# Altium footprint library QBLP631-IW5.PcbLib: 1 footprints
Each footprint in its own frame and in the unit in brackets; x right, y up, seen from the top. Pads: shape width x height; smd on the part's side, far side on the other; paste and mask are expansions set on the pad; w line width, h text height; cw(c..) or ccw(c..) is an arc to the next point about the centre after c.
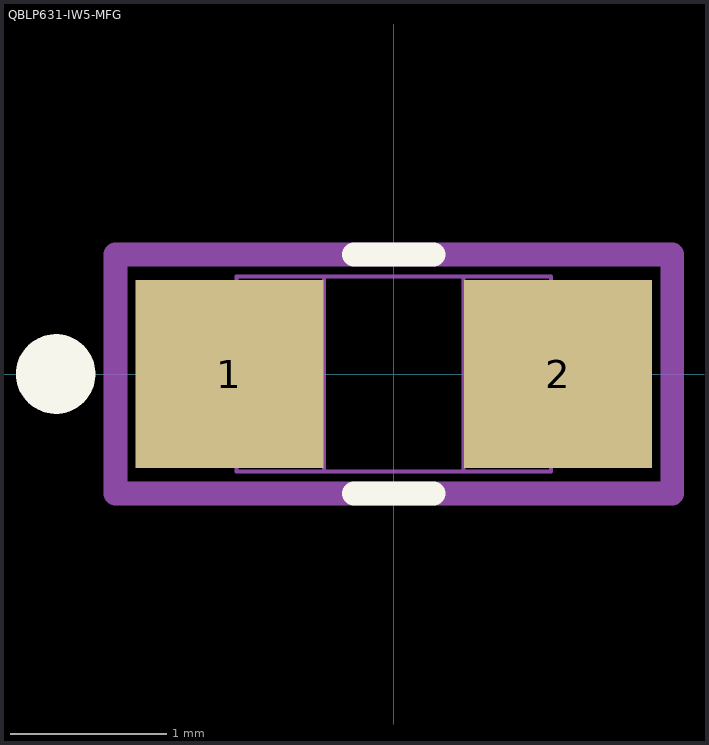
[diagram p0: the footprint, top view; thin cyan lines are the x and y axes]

## QBLP631-IW5-MFG [mm]
pads (2):
  rect 1.2x1.2 smd paste+0 mask+0: 1(-1.05,0) 2(1.05,0)
Top Overlay:
  circle w0.254: c-2.159,0 r0.127
  lines w0.152: -0.254,-0.762 0.254,-0.762 ; -0.254,0.762 0.254,0.762
Mechanical 5:
  lines w0.152: -1.778,-0.762 1.778,-0.762 1.778,0.762 -1.778,0.762 -1.778,-0.762
Mechanical 13:
  lines w0.025: -1.003,-0.622 -1.003,0.622 ; -1.003,-0.622 1.003,-0.622 ; -1.003,-0.622 -0.445,-0.622 -0.445,0.622 -1.003,0.622 ; -1.003,-0.622 -1.003,0.622 ; -1.003,0.622 1.003,0.622 ; 1.003,-0.622 1.003,0.622 ; 1.003,-0.622 1.003,0.622 ; 1.003,-0.622 0.445,-0.622 0.445,0.622 1.003,0.622
Mechanical 15:
  lines w0.152: -1.778,-0.762 -1.778,0.762 1.778,0.762 1.778,-0.762 -1.778,-0.762
3D body "QBLP631_MONO.step": height 0.8, standoff 0, extent -0.908,-0.625 1.092,0.625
